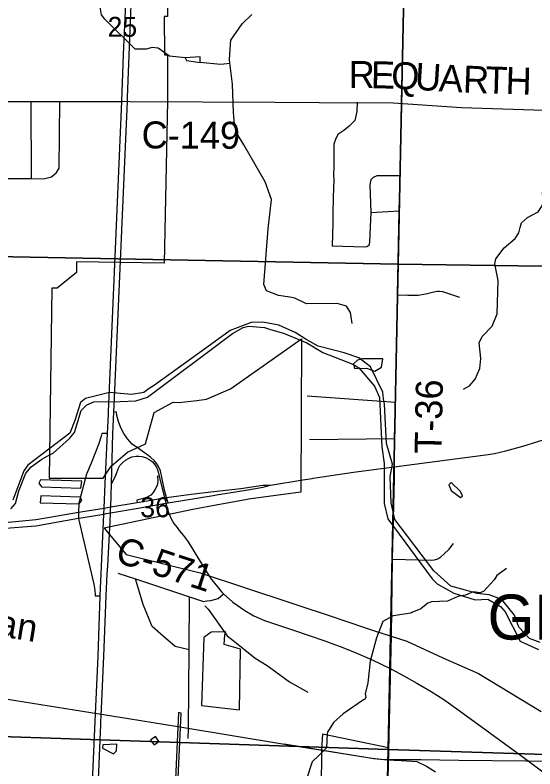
# Model space of a CAD drawing. Extents: x 0 to 68.9, y -26.1 to 22.
# Drawn here: x 6.469 to 7.562, y 16.802 to 18.387 of the extents above; entities that cross this region are included whole.
import ezdxf

# ---------------------------------------------------------------- set-up
doc = ezdxf.new("R2010")
doc.units = 0
for name, color, linetype in [('GM_X_City_Street', 7, 'Continuous'), ('GM_X_Corporation', 7, 'Continuous'), ('GM_X_Corporation_Text', 7, 'Continuous'), ('GM_X_County_Road', 7, 'Continuous'), ('GM_X_County_Road_Text', 7, 'Continuous'), ('GM_X_Interchange_Ramps', 7, 'Continuous'), ('GM_X_Major_River', 7, 'Continuous'), ('GM_X_Minor_Lake', 7, 'Continuous'), ('GM_X_Minor_River', 7, 'Continuous'), ('GM_X_Rail_Line', 7, 'Continuous'), ('GM_X_Rail_Line_Text', 7, 'Continuous'), ('GM_X_Section_Text', 7, 'Continuous'), ('GM_X_State_Route', 7, 'Continuous'), ('GM_X_Township_Road', 7, 'Continuous'), ('GM_X_Township_Road_Text', 7, 'Continuous'), ('GM_X_US_Route', 7, 'Continuous')]:
    doc.layers.add(name, color=color, linetype=linetype)

msp = doc.modelspace()

# ---------------------------------------------------------------- linework, layer by layer
at = {"layer": 'GM_X_City_Street'}
msp.add_line((6.5033, 18.0432), (6.503, 18.2055), dxfattribs=at)
for points in [[(6.3852, 18.0439), (6.4427, 18.0436), (6.5033, 18.0432), (6.5291, 18.043), (6.5453, 18.047), (6.5562, 18.0558), (6.5615, 18.0651), (6.5632, 18.2056)], [(6.8346, 17.0526), (6.8058, 17.0596), (6.7802, 17.0814), (6.7571, 17.1019), (6.7379, 17.148), (6.7224, 17.2017)], [(6.833, 16.8665), (6.8332, 16.8871), (6.8346, 17.0526), (6.8355, 17.1643)], [(6.8678, 17.1452), (6.8745, 17.138), (6.9149, 17.0823), (6.9264, 17.0728), (6.9735, 17.0355), (6.9985, 17.0199), (7.0457, 16.9856), (7.0842, 16.9638)]]:
    msp.add_lwpolyline(points, dxfattribs=at)
at = {"layer": 'GM_X_Corporation'}
for points in [[(6.2983, 18.8857), (7.2954, 18.8682), (7.2743, 17.8636), (6.2791, 17.8826)], [(7.2954, 18.8682), (8.2978, 18.8494), (8.2824, 17.8496), (7.2743, 17.8636)], [(6.2791, 17.8826), (7.2743, 17.8636), (7.2528, 16.8431), (6.2515, 16.877)], [(7.2743, 17.8636), (8.2824, 17.8496), (8.2721, 16.8167), (8.024, 16.8186), (7.2528, 16.8431)], [(6.2515, 16.877), (7.2528, 16.8431), (7.2305, 15.8522), (6.224, 15.8733)], [(7.2528, 16.8431), (8.024, 16.8186), (8.019, 15.8387), (7.2304, 15.8453), (7.2305, 15.8522)]]:
    msp.add_lwpolyline(points, close=True, dxfattribs=at)
for points in [[(6.7872, 18.6414), (6.7897, 18.3841), (6.7825, 18.3842), (6.7828, 18.3033), (6.7896, 18.3032), (6.7891, 18.206), (6.7826, 17.8655), (6.5985, 17.8686), (6.5983, 17.8459), (6.5577, 17.813), (6.5463, 17.813), (6.5406, 17.4138), (6.6543, 17.4139), (6.671, 17.4389), (6.7051, 17.4681), (6.7429, 17.486), (6.7616, 17.5515), (6.8014, 17.5735), (6.8131, 17.5727), (6.8513, 17.5772), (6.8716, 17.58), (6.922, 17.6016), (7.0709, 17.7068), (7.0693, 17.3842), (6.9595, 17.3692), (6.9565, 17.3687), (6.8993, 17.3581), (6.8952, 17.3574), (6.8426, 17.3475), (6.7728, 17.3331), (6.6565, 17.3083), (6.7024, 17.253), (6.8581, 17.2145), (7.144, 17.12), (7.147, 17.1183), (7.2241, 17.0927), (7.2921, 17.0711), (7.3682, 17.036), (7.4428, 17.0028), (7.5744, 16.9229)], [(6.796, 16.4357), (6.8179, 16.9198), (6.8124, 16.9207), (6.8047, 16.7504)], [(7.2446, 16.4546), (7.2541, 16.8466), (7.1153, 16.8758), (7.1128, 16.8426), (7.1107, 16.5937)]]:
    msp.add_lwpolyline(points, dxfattribs=at)
at = {"layer": 'GM_X_County_Road'}
for points in [[(6.3956, 18.2053), (6.4444, 18.2054), (6.4817, 18.2054), (6.4868, 18.2054)], [(6.4868, 18.2054), (6.503, 18.2055), (6.5632, 18.2056)], [(6.5632, 18.2056), (6.612, 18.2056), (6.6191, 18.2056)], [(6.6191, 18.2056), (6.6933, 18.2057), (6.7052, 18.2058), (6.7103, 18.2057)], [(6.7103, 18.2057), (7.0151, 18.204), (7.1082, 18.2034)], [(7.1082, 18.2034), (7.2634, 18.2025), (7.4069, 18.1931), (7.6893, 18.1835), (8.1149, 18.1922)], [(6.6853, 17.214), (6.7224, 17.2017), (6.8355, 17.1643), (6.8565, 17.1574), (6.8648, 17.1547), (6.8722, 17.1555)], [(6.8722, 17.1555), (6.8805, 17.1565), (6.8962, 17.1607), (6.9073, 17.1703)]]:
    msp.add_lwpolyline(points, dxfattribs=at)
at = {"layer": 'GM_X_Interchange_Ramps'}
for p, q in [((6.7909, 17.3616), (6.7874, 17.3732)), ((6.6376, 17.1666), (6.6482, 17.1662))]:
    msp.add_line(p, q, dxfattribs=at)
for points in [[(6.7874, 17.3732), (6.7828, 17.3885), (6.7785, 17.412), (6.7747, 17.4292), (6.7689, 17.4408), (6.762, 17.4501), (6.7534, 17.458), (6.7283, 17.4759), (6.715, 17.4852), (6.705, 17.4964), (6.6975, 17.5074), (6.6912, 17.5192), (6.6864, 17.5325), (6.6832, 17.5454), (6.6825, 17.5525), (6.6769, 17.5528)], [(6.6633, 17.5075), (6.6515, 17.5076), (6.65, 17.5016), (6.6441, 17.4841), (6.6292, 17.4449), (6.6193, 17.4218), (6.6133, 17.4011), (6.6079, 17.3797), (6.6033, 17.3614), (6.6024, 17.3418), (6.6027, 17.3294)], [(6.7717, 17.4176), (6.7674, 17.4174), (6.7683, 17.4148), (6.7688, 17.4117), (6.769, 17.4057), (6.7676, 17.3985), (6.7638, 17.3906), (6.7592, 17.3833), (6.7543, 17.378), (6.7453, 17.373), (6.7362, 17.3699), (6.725, 17.3675), (6.7257, 17.3626)], [(6.6027, 17.3294), (6.6031, 17.3251), (6.6343, 17.1905), (6.6367, 17.1782), (6.6376, 17.1681), (6.6376, 17.1666)]]:
    msp.add_lwpolyline(points, dxfattribs=at)
at = {"layer": 'GM_X_Major_River'}
for points in [[(6.4602, 17.3494), (6.4699, 17.3603), (6.4769, 17.3871), (6.492, 17.4244), (6.5026, 17.4372), (6.5253, 17.4535), (6.5365, 17.4601), (6.5488, 17.4663), (6.5836, 17.4968), (6.5937, 17.5095), (6.6079, 17.556), (6.6196, 17.5676), (6.6345, 17.5741), (6.6898, 17.575), (6.7229, 17.5763), (6.7474, 17.5838), (6.9258, 17.7177), (6.9481, 17.7302), (6.9596, 17.733), (6.9934, 17.7305), (7.0055, 17.7264), (7.0335, 17.7183), (7.0819, 17.6981), (7.1158, 17.6777), (7.1789, 17.6534), (7.1913, 17.6455), (7.2241, 17.607), (7.2351, 17.5832), (7.2396, 17.4798), (7.245, 17.4444), (7.245, 17.3601), (7.2524, 17.328), (7.3456, 17.2017), (7.3564, 17.1916), (7.3911, 17.1716), (7.4361, 17.1578), (7.4628, 17.1592), (7.4895, 17.1439), (7.4988, 17.1327), (7.5308, 17.071), (7.5693, 17.0532)], [(7.5722, 17.0683), (7.5499, 17.0763), (7.5275, 17.1007), (7.5189, 17.1255), (7.4917, 17.1587), (7.4656, 17.1687), (7.4402, 17.1711), (7.4156, 17.1784), (7.3849, 17.1865), (7.3493, 17.2187), (7.2672, 17.3266), (7.2591, 17.3617), (7.2571, 17.4172), (7.2621, 17.4429), (7.2496, 17.4868), (7.2451, 17.5693), (7.2434, 17.5804), (7.2417, 17.5945), (7.2157, 17.6478), (7.1917, 17.6668), (7.1607, 17.6773), (7.1061, 17.6912), (7.0824, 17.7041), (7.0579, 17.7198), (7.0232, 17.7349), (6.9894, 17.7416), (6.965, 17.7409), (6.9213, 17.7238), (6.8878, 17.6994), (6.7623, 17.609), (6.7512, 17.6024), (6.7396, 17.5938), (6.714, 17.5894), (6.6673, 17.5937), (6.6172, 17.5809), (6.6063, 17.5724), (6.5946, 17.535), (6.5842, 17.5082), (6.4958, 17.4411), (6.4876, 17.4291), (6.4643, 17.3672)]]:
    msp.add_lwpolyline(points, dxfattribs=at)
at = {"layer": 'GM_X_Minor_Lake'}
for points in [[(6.8581, 18.2876), (6.858, 18.299), (6.8267, 18.2973)], [(6.8267, 18.2973), (6.8293, 18.2912), (6.8581, 18.2876)], [(7.2417, 17.6641), (7.199, 17.6645), (7.1887, 17.6613), (7.1802, 17.6539), (7.1827, 17.6443)], [(7.1827, 17.6443), (7.2078, 17.6446), (7.2248, 17.6386), (7.2391, 17.6467), (7.2417, 17.6641)], [(6.6091, 17.4076), (6.5224, 17.4103), (6.5188, 17.4032), (6.5244, 17.3955)], [(6.5244, 17.3955), (6.6073, 17.3925), (6.6091, 17.4076)], [(7.3853, 17.4043), (7.3803, 17.3999), (7.3857, 17.3876), (7.4053, 17.3732)], [(7.4053, 17.3732), (7.4091, 17.3762), (7.4051, 17.3857), (7.3853, 17.4043)], [(6.6058, 17.3739), (6.5229, 17.3765), (6.5219, 17.3621)], [(6.5219, 17.3621), (6.6037, 17.3595), (6.6095, 17.3673), (6.6058, 17.3739)], [(6.9084, 17.0637), (6.9096, 17.0846), (6.912, 17.0906), (6.8815, 17.09), (6.8657, 17.0785), (6.8611, 16.9354)], [(6.8611, 16.9354), (6.9409, 16.9267), (6.9425, 17.0543), (6.9084, 17.0637)], [(6.7643, 16.8703), (6.7535, 16.8629), (6.7617, 16.8529)], [(6.7617, 16.8529), (6.7714, 16.8599), (6.7643, 16.8703)], [(6.6536, 16.853), (6.6527, 16.8458), (6.6757, 16.8344)], [(6.6757, 16.8344), (6.6819, 16.8407), (6.6826, 16.8544), (6.6536, 16.853)]]:
    msp.add_lwpolyline(points, dxfattribs=at)
at = {"layer": 'GM_X_Minor_River'}
for points in [[(6.8267, 18.2973), (6.7933, 18.3009), (6.7696, 18.3177), (6.7571, 18.3191), (6.7444, 18.3155), (6.7212, 18.3155), (6.6577, 18.3782), (6.651, 18.3878), (6.639, 18.4598), (6.6417, 18.4837), (6.6495, 18.5113), (6.6451, 18.5522)], [(7.1775, 17.7386), (7.174, 17.7621), (7.1656, 17.7749), (7.1457, 17.7806), (7.0817, 17.7802), (7.0569, 17.7921), (7.0467, 17.794), (7.0229, 17.7978), (6.9977, 17.8075), (6.9917, 17.8206), (7.0007, 17.9376), (7.0078, 17.9994), (6.9947, 18.0367), (6.9498, 18.1144), (6.9357, 18.1374), (6.9304, 18.1578), (6.9282, 18.1822), (6.9262, 18.2415), (6.9199, 18.2925), (6.9201, 18.3054), (6.9226, 18.3343), (6.9465, 18.3685), (6.9666, 18.3879)], [(6.9208, 18.2853), (6.9007, 18.2834), (6.8581, 18.2876)], [(7.4117, 17.6007), (7.4239, 17.6076), (7.4362, 17.6216), (7.4457, 17.6441), (7.4476, 17.6654), (7.4442, 17.6982), (7.4504, 17.7113), (7.4717, 17.733), (7.4821, 17.7593), (7.4846, 17.8293), (7.4774, 17.8642), (7.4793, 17.8744), (7.4969, 17.8981), (7.5197, 17.9175), (7.5277, 17.929), (7.5308, 17.9407), (7.533, 17.9505), (7.5456, 17.9615), (7.5685, 17.9736), (7.5765, 17.9859), (7.5804, 17.9984), (7.5774, 18.0118), (7.5794, 18.0254), (7.5875, 18.0381)], [(7.5021, 17.224), (7.4814, 17.2091), (7.4761, 17.1996), (7.4542, 17.1764), (7.4466, 17.1726), (7.4314, 17.1745), (7.4159, 17.1676), (7.3992, 17.1649), (7.378, 17.1554), (7.3443, 17.1535), (7.3364, 17.1508), (7.322, 17.1386), (7.3026, 17.1314), (7.3004, 17.1298), (7.2636, 17.1245), (7.2417, 17.1124)], [(7.2417, 17.1124), (7.2285, 17.0777), (7.215, 17.0291), (7.2105, 16.9836), (7.2049, 16.96), (7.2064, 16.9536), (7.2042, 16.9482), (7.2011, 16.9479), (7.1588, 16.9182), (7.138, 16.9003), (7.1255, 16.8798), (7.1251, 16.8771), (7.1233, 16.8471), (7.1074, 16.8308), (7.0934, 16.8171), (7.081, 16.7791), (7.0834, 16.7404), (7.0804, 16.7252), (7.077, 16.6994), (7.0668, 16.6808), (7.054, 16.666), (7.0283, 16.6477), (7.0197, 16.6386)]]:
    msp.add_lwpolyline(points, dxfattribs=at)
at = {"layer": 'GM_X_Rail_Line'}
for points in [[(6.2511, 16.9826), (6.4706, 16.9463), (6.5934, 16.9267), (6.7076, 16.9081), (6.8114, 16.8914), (7.0351, 16.8547), (7.2197, 16.8249), (7.2509, 16.8216), (7.2805, 16.82), (7.3134, 16.8183), (7.334, 16.8085), (7.3529, 16.7961)], [(7.0349, 16.8553), (7.2232, 16.8244), (7.244, 16.8223), (7.3216, 16.8225)], [(7.3216, 16.8225), (7.4015, 16.821), (7.6832, 16.8183), (7.7919, 16.8163), (7.9771, 16.8149), (8.2259, 16.8141), (8.727, 16.8103)]]:
    msp.add_lwpolyline(points, dxfattribs=at)
at = {"layer": 'GM_X_State_Route'}
msp.add_line((6.6024, 17.3418), (6.6118, 17.3434), dxfattribs=at)
for points in [[(6.6118, 17.3434), (6.6563, 17.3508), (6.67, 17.3531), (6.7257, 17.3626), (6.7829, 17.3722)], [(6.6606, 17.339), (6.6695, 17.3404), (6.7275, 17.3505), (6.7857, 17.3609)], [(6.7857, 17.3609), (6.7871, 17.3557), (6.7912, 17.3417), (6.797, 17.3279), (6.8026, 17.3185), (6.8095, 17.3098)], [(6.3258, 17.3148), (6.3353, 17.3183), (6.3555, 17.318), (6.4038, 17.3183), (6.4402, 17.3199), (6.4769, 17.3229), (6.5124, 17.3269), (6.5423, 17.3313), (6.6024, 17.3418)], [(6.6124, 17.331), (6.6557, 17.3381), (6.6606, 17.339)], [(6.3258, 17.3148), (6.3345, 17.3092), (6.3748, 17.3066), (6.4406, 17.3075), (6.5126, 17.3136), (6.6027, 17.3294), (6.6124, 17.331)], [(6.8095, 17.3098), (6.8141, 17.3039), (6.8225, 17.2937), (6.8328, 17.28), (6.8526, 17.2476)], [(6.8526, 17.2476), (6.8797, 17.2031), (6.9027, 17.1744), (6.9073, 17.1703), (6.9264, 17.153), (6.9519, 17.1355), (6.9706, 17.1245), (6.9934, 17.1144), (7.052, 17.0948), (7.087, 17.0827), (7.1199, 17.072), (7.1427, 17.0633)], [(7.1427, 17.0633), (7.1546, 17.0588), (7.1838, 17.0468), (7.218, 17.0321), (7.2598, 17.0124), (7.2861, 16.9984), (7.3137, 16.9829), (7.3436, 16.965), (7.3699, 16.9483), (7.4023, 16.9251), (7.5313, 16.8313), (7.5557, 16.8128), (7.6031, 16.7775), (7.9814, 16.4979)]]:
    msp.add_lwpolyline(points, dxfattribs=at)
at = {"layer": 'GM_X_Township_Road'}
for p, q in [((7.2167, 17.9717), (7.2765, 17.9752)), ((7.0826, 17.5865), (7.2683, 17.5733)), ((7.0879, 17.4951), (7.2667, 17.4969))]:
    msp.add_line(p, q, dxfattribs=at)
for points in [[(7.2811, 18.2034), (7.2956, 18.865), (7.309, 19.581)], [(7.188, 18.204), (7.1876, 18.1846), (7.1828, 18.1657), (7.1714, 18.1535), (7.1599, 18.1446), (7.1472, 18.1357), (7.1423, 18.1257), (7.1389, 18.1154), (7.1392, 18.1009), (7.1392, 18.0844), (7.1389, 18.0663), (7.1382, 18.0527), (7.1387, 18.0391), (7.1383, 18.0235), (7.1378, 18.0034), (7.1368, 17.9688), (7.1366, 17.9502), (7.1361, 17.9259), (7.1356, 17.9013)], [(7.26, 17.0827), (7.2624, 17.2431), (7.2664, 17.4132), (7.2667, 17.4969), (7.2683, 17.5733), (7.2729, 17.7992), (7.2765, 17.9752), (7.278, 18.0488), (7.2811, 18.2034)], [(7.278, 18.0488), (7.2294, 18.0491), (7.2214, 18.0458), (7.2167, 18.0408), (7.2145, 18.0305), (7.2167, 17.9717), (7.2162, 17.9571), (7.2141, 17.9096), (7.2126, 17.9025), (7.2081, 17.8999), (7.2031, 17.8994), (7.1356, 17.9013)], [(7.2729, 17.7992), (7.2943, 17.7982), (7.3038, 17.7981), (7.3163, 17.7986), (7.3326, 17.8014), (7.3464, 17.8048), (7.3558, 17.8068), (7.3607, 17.8069), (7.3671, 17.8058), (7.3842, 17.8002), (7.4028, 17.7938)], [(7.2624, 17.2431), (7.3449, 17.241), (7.3508, 17.242), (7.3575, 17.2441), (7.3636, 17.2483), (7.3701, 17.2535), (7.3813, 17.2646), (7.3902, 17.2765)], [(7.2542, 16.84), (7.2542, 16.841), (7.2571, 16.9638), (7.26, 17.0827)], [(7.2449, 16.4456), (7.2449, 16.4466), (7.2542, 16.84)]]:
    msp.add_lwpolyline(points, dxfattribs=at)
at = {"layer": 'GM_X_US_Route'}
for p, q in [((6.6769, 17.5528), (6.6781, 17.5824)), ((7.0737, 17.41), (7.0934, 17.4132))]:
    msp.add_line(p, q, dxfattribs=at)
for points in [[(6.6651, 17.5474), (6.6654, 17.5534), (6.6933, 18.2057), (6.6968, 18.3043), (6.7024, 18.4282), (6.7084, 18.5276), (6.7196, 18.6432), (6.7431, 18.8737), (6.7694, 19.1253)], [(6.7055, 18.2137), (6.714, 18.4276), (6.7211, 18.5216), (6.7311, 18.6427), (6.7553, 18.8735)], [(6.6781, 17.5824), (6.7052, 18.2058), (6.7055, 18.2137)], [(6.6586, 17.4027), (6.6633, 17.5075), (6.6651, 17.5474)], [(6.6719, 17.402), (6.6748, 17.5069), (6.6769, 17.5528)], [(7.0934, 17.4132), (7.0956, 17.4133), (7.1801, 17.4263), (7.4635, 17.4631), (7.4764, 17.4653), (7.5001, 17.4708), (7.5361, 17.4809), (7.5992, 17.5007)], [(6.6719, 17.402), (6.6797, 17.4162), (6.6819, 17.4236), (6.6855, 17.4334), (6.6895, 17.4405), (6.6945, 17.446), (6.7008, 17.4516), (6.7072, 17.4551), (6.7144, 17.4583), (6.7238, 17.4597), (6.729, 17.4597), (6.7352, 17.4588), (6.7432, 17.4571), (6.7506, 17.4527), (6.7569, 17.4486), (6.7611, 17.4434), (6.7665, 17.4364), (6.7687, 17.431), (6.7706, 17.4239), (6.7717, 17.4176), (6.7829, 17.3722), (6.7857, 17.3609)], [(6.6482, 17.1662), (6.6557, 17.3381), (6.6563, 17.3508), (6.6586, 17.4027)], [(6.6696, 17.3425), (6.6698, 17.3477), (6.67, 17.3531), (6.6719, 17.402)], [(6.7829, 17.3722), (6.7874, 17.3732), (6.839, 17.38), (6.8805, 17.385), (6.9432, 17.3921), (6.9898, 17.3992), (7.0048, 17.399)], [(7.0048, 17.399), (7.0057, 17.3991), (7.0737, 17.41)], [(6.8926, 17.3784), (6.9543, 17.3882), (6.9906, 17.3944), (7.0048, 17.399)], [(6.7857, 17.3609), (6.7909, 17.3616), (6.8854, 17.3772), (6.8926, 17.3784)], [(6.6686, 17.3226), (6.6695, 17.3404), (6.6696, 17.3425)], [(6.6628, 17.2135), (6.6637, 17.2294), (6.6686, 17.3226)], [(6.6493, 16.8953), (6.6496, 16.9022), (6.6501, 16.9133), (6.6556, 17.0392), (6.6603, 17.1658), (6.6628, 17.2135)], [(6.6145, 16.3735), (6.6376, 16.9027), (6.6435, 17.0397), (6.6482, 17.1662)], [(6.5094, 15.8686), (6.5411, 15.9345), (6.5549, 15.9701), (6.5677, 16.0065), (6.5796, 16.0442), (6.5936, 16.0943), (6.6021, 16.1351), (6.6109, 16.1845), (6.618, 16.2322), (6.6218, 16.279), (6.6266, 16.373), (6.6493, 16.8953)]]:
    msp.add_lwpolyline(points, dxfattribs=at)

# ---------------------------------------------------------------- texts
at = {"layer": 'GM_X_Corporation_Text'}
msp.add_text('GREENVILLE', height=0.0947, rotation=0, dxfattribs=at).set_placement((7.4618, 17.0743))
at = {"layer": 'GM_X_County_Road_Text'}
for s, height, rotation, p in [('R', 0.0568, 359.4536, (7.1699, 18.2339)), ('E', 0.0568, 358.7442, (7.2163, 18.2334)), ('Q', 0.0568, 357.3835, (7.2585, 18.2325)), ('U', 0.0568, 356.3657, (7.3081, 18.2302)), ('A', 0.0568, 356.8794, (7.3586, 18.227)), ('R', 0.0568, 357.8251, (7.4095, 18.2243)), ('T', 0.0568, 358.3166, (7.4567, 18.2225)), ('H', 0.0568, 358.3551, (7.4992, 18.2212)), ('C-149', 0.05682, 359.7247, (6.7349, 18.1068)), ('C-571', 0.05682, 341.7156, (6.6769, 17.2385))]:
    msp.add_text(s, height=height, rotation=rotation, dxfattribs=at).set_placement(p)
at = {"layer": 'GM_X_Rail_Line_Text'}
msp.add_text('R.J. Corman', height=0.056629, rotation=350.7396, dxfattribs=at).set_placement((6.0918, 17.1374))
at = {"layer": 'GM_X_Section_Text'}
for s, p in [('25', (6.6634, 18.3414)), ('36', (6.7322, 17.3314))]:
    msp.add_text(s, height=0.04186, rotation=0, dxfattribs=at).set_placement(p)
at = {"layer": 'GM_X_Township_Road_Text'}
msp.add_text('T-36', height=0.05682, rotation=88.9531, dxfattribs=at).set_placement((7.3654, 17.4644))

doc.saveas('drawing.dxf')
